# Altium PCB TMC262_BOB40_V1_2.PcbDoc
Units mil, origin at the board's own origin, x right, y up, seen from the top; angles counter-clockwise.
Board outline 1500 x 1200 mil, 4 copper layers (Top, GND, VM, Bottom), stack 27.719 mil thick; 33 components, 31 nets, 107 pads, 155 vias.
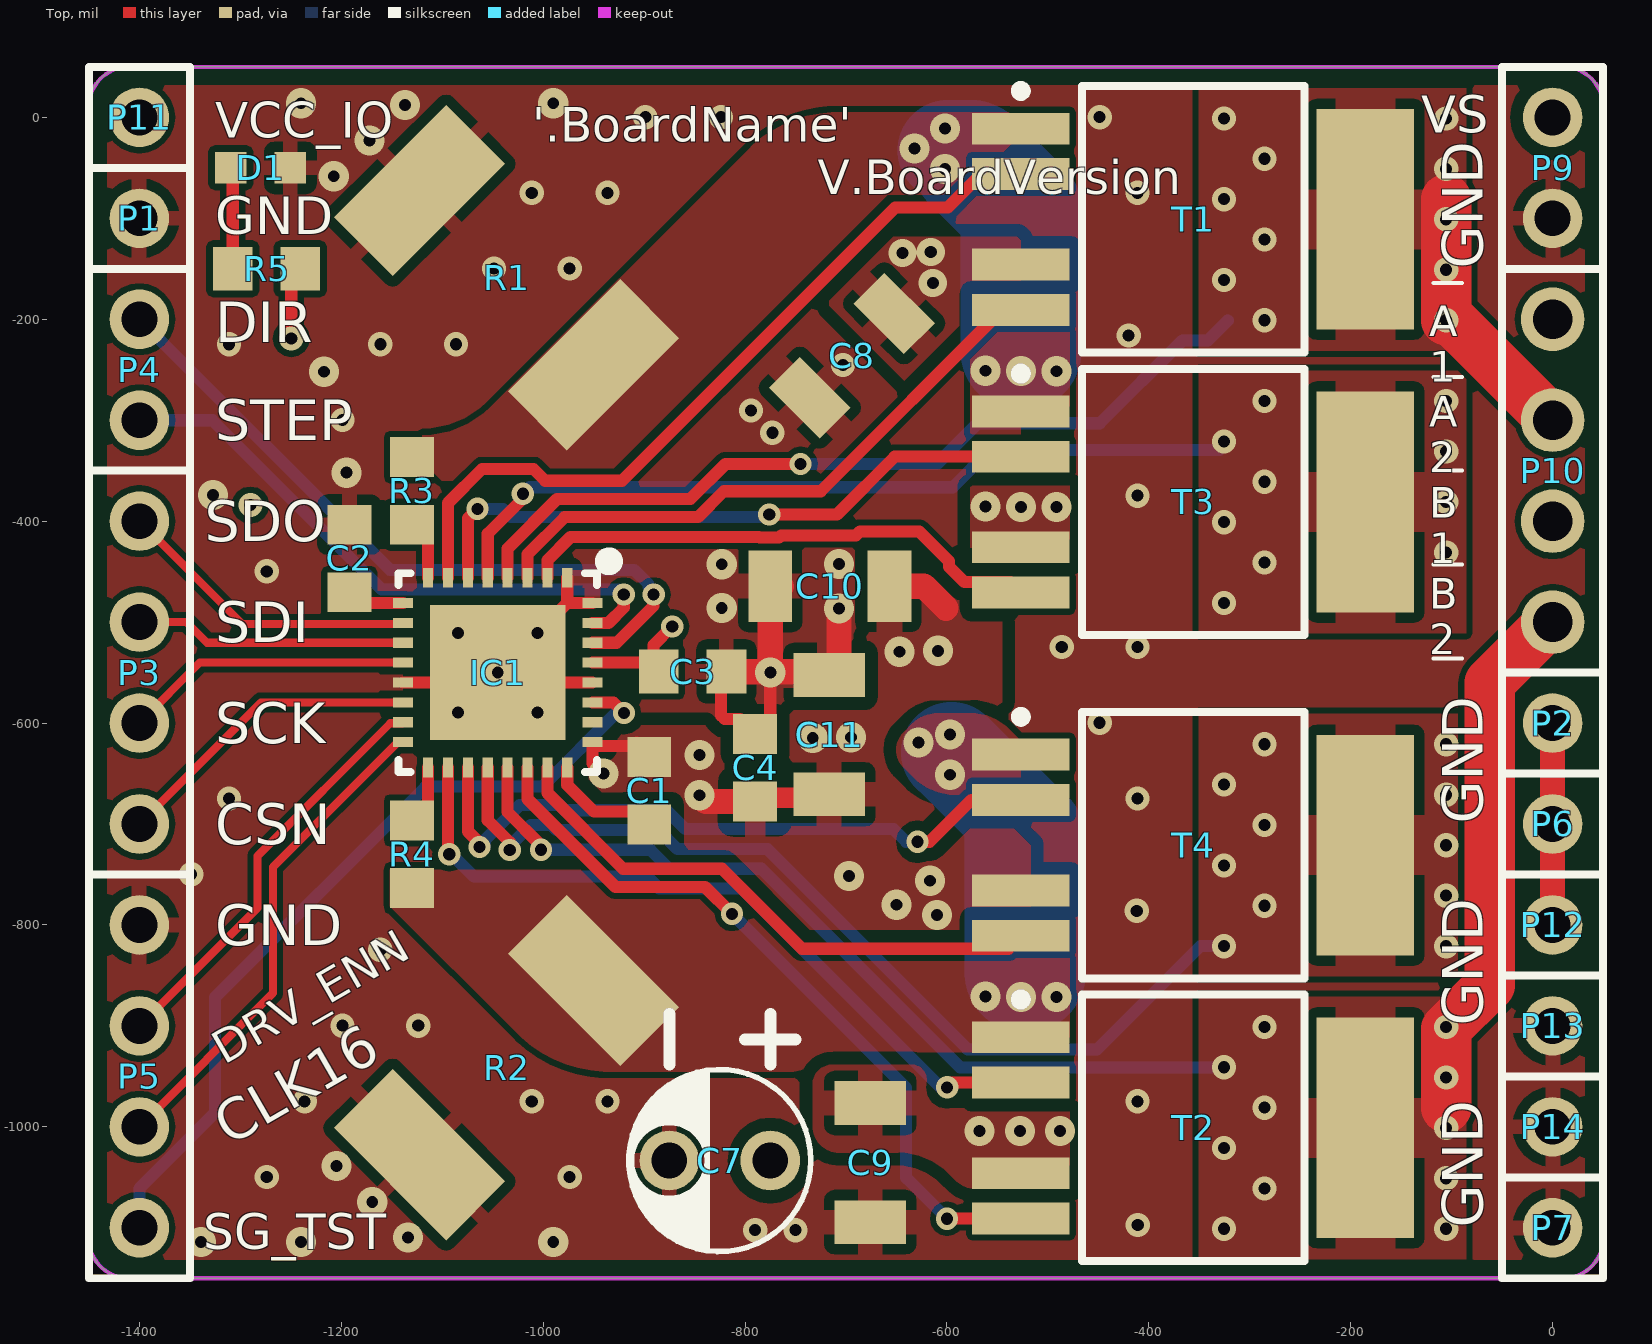
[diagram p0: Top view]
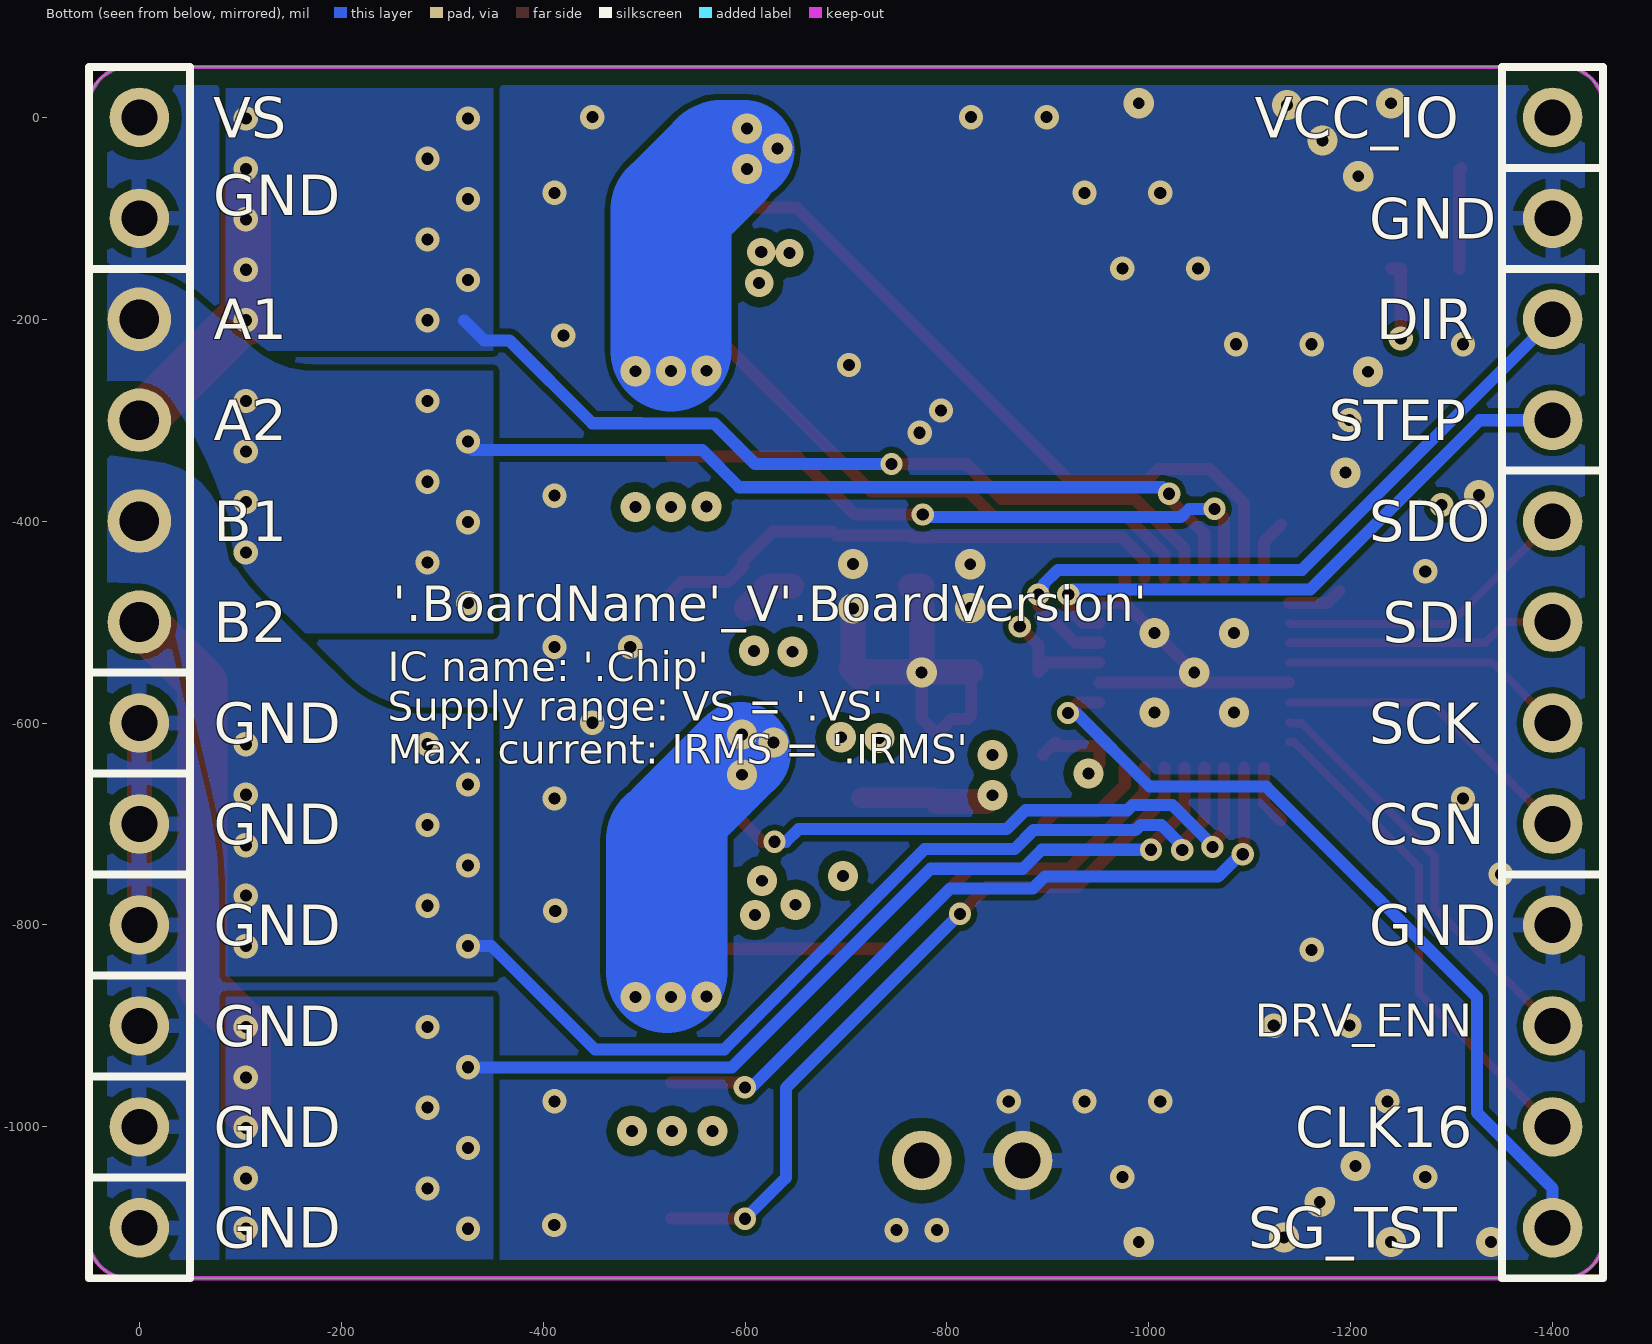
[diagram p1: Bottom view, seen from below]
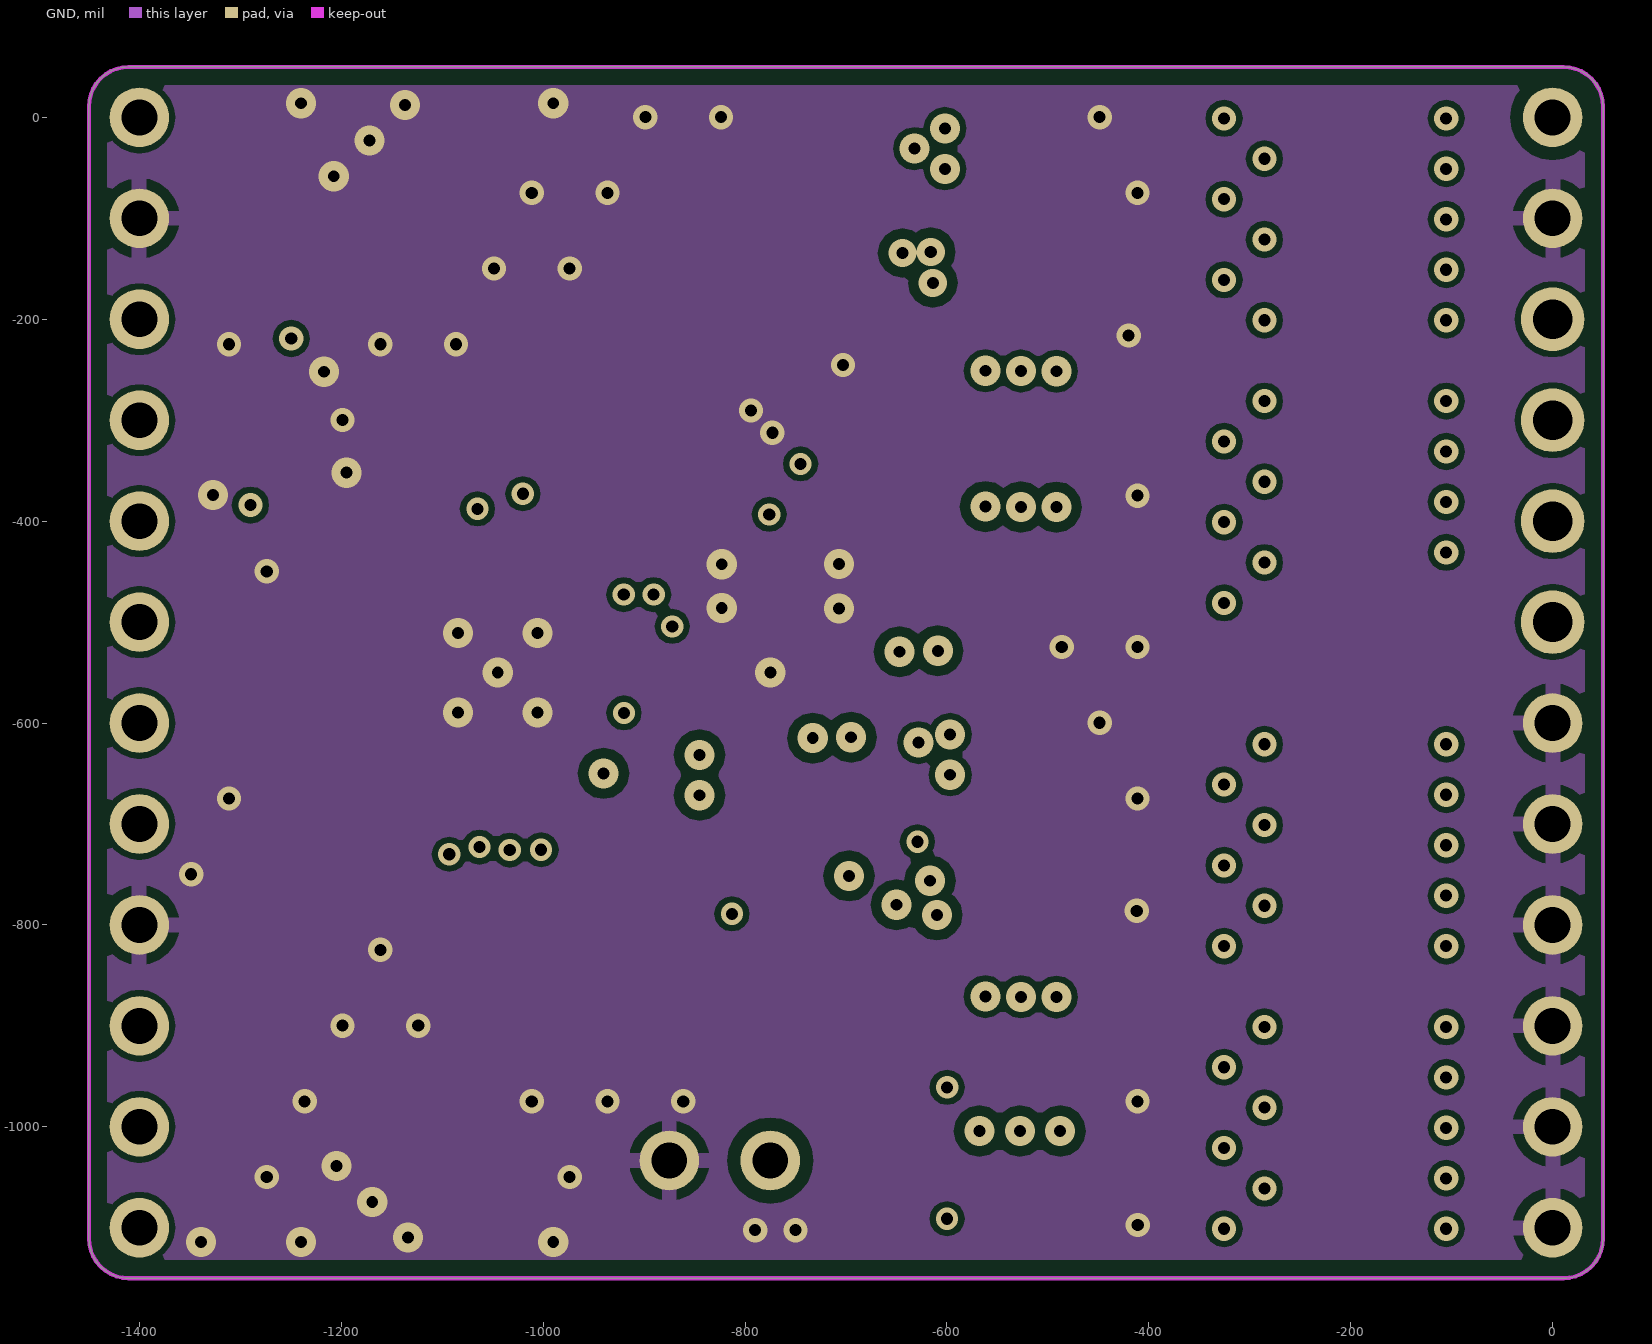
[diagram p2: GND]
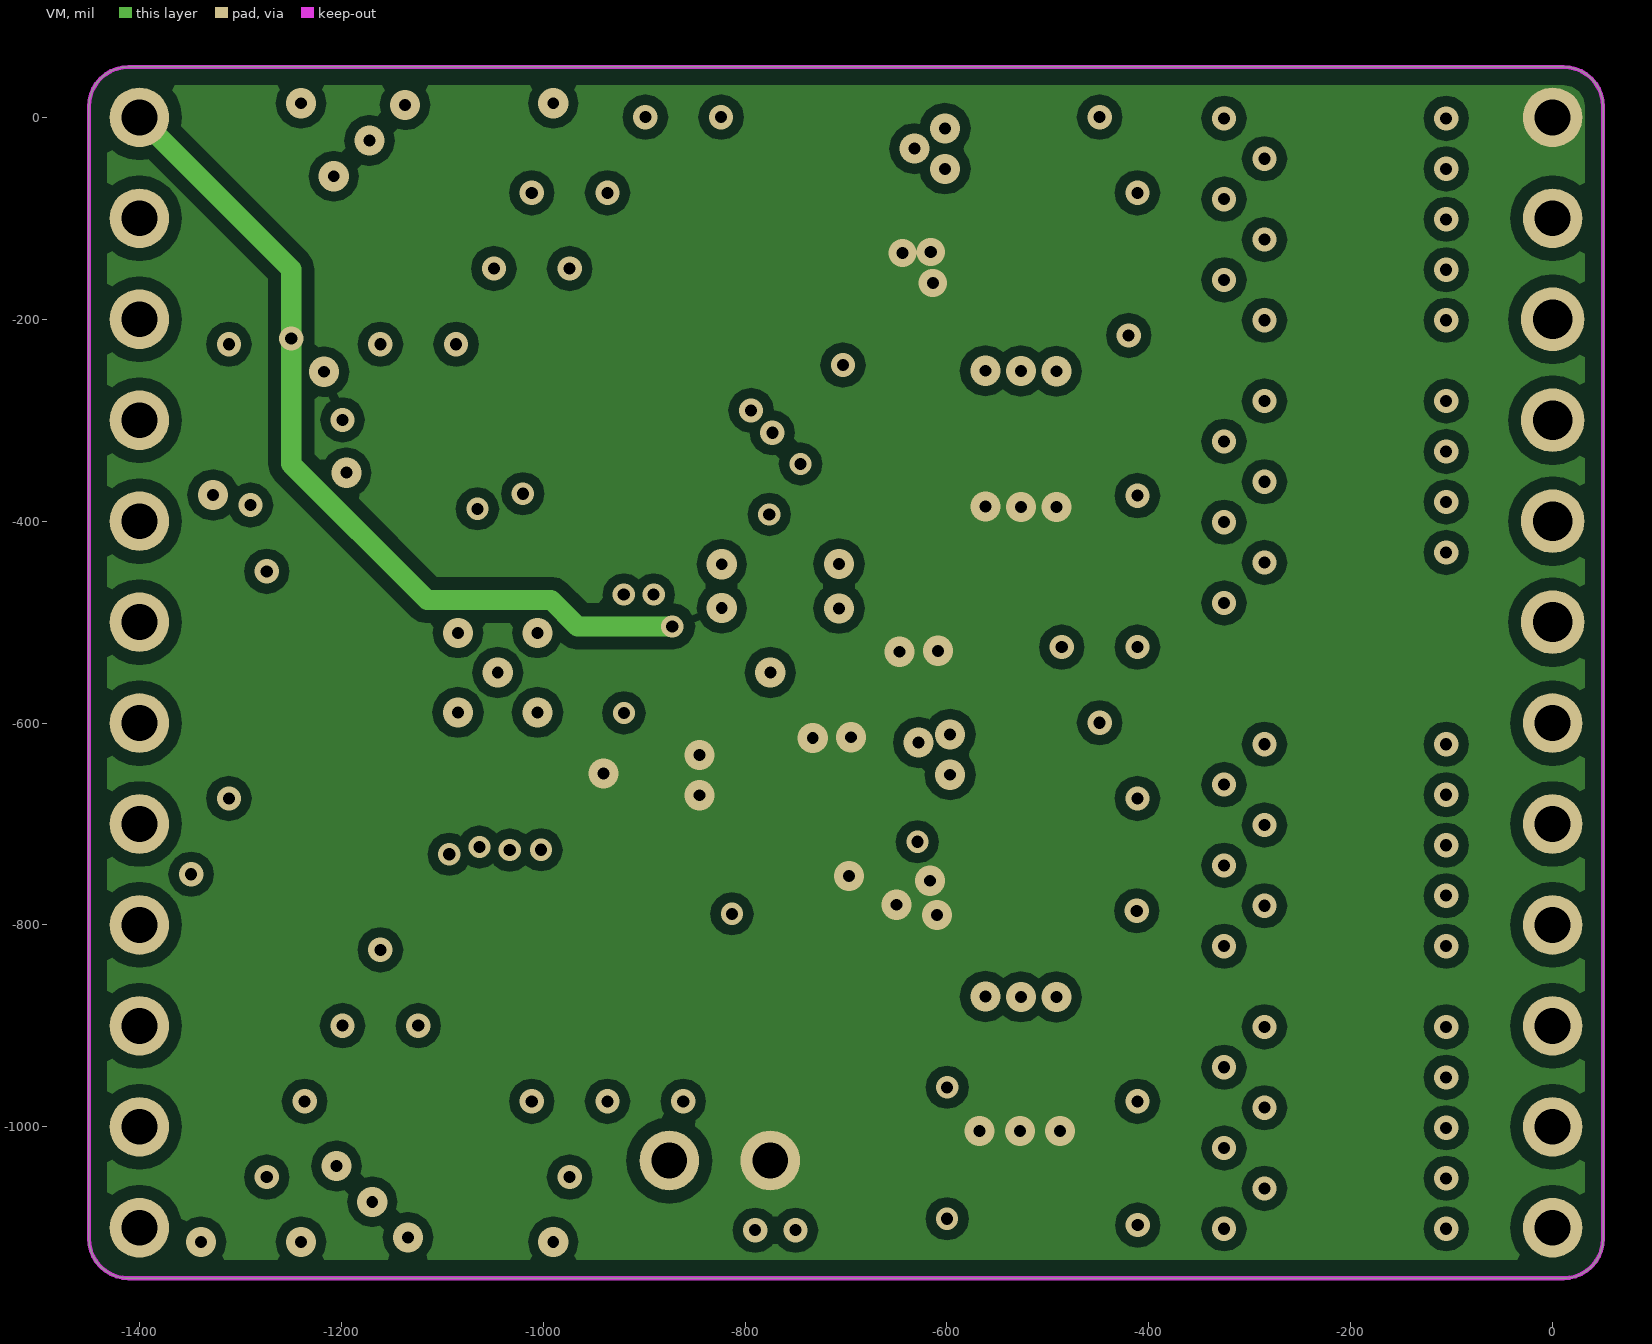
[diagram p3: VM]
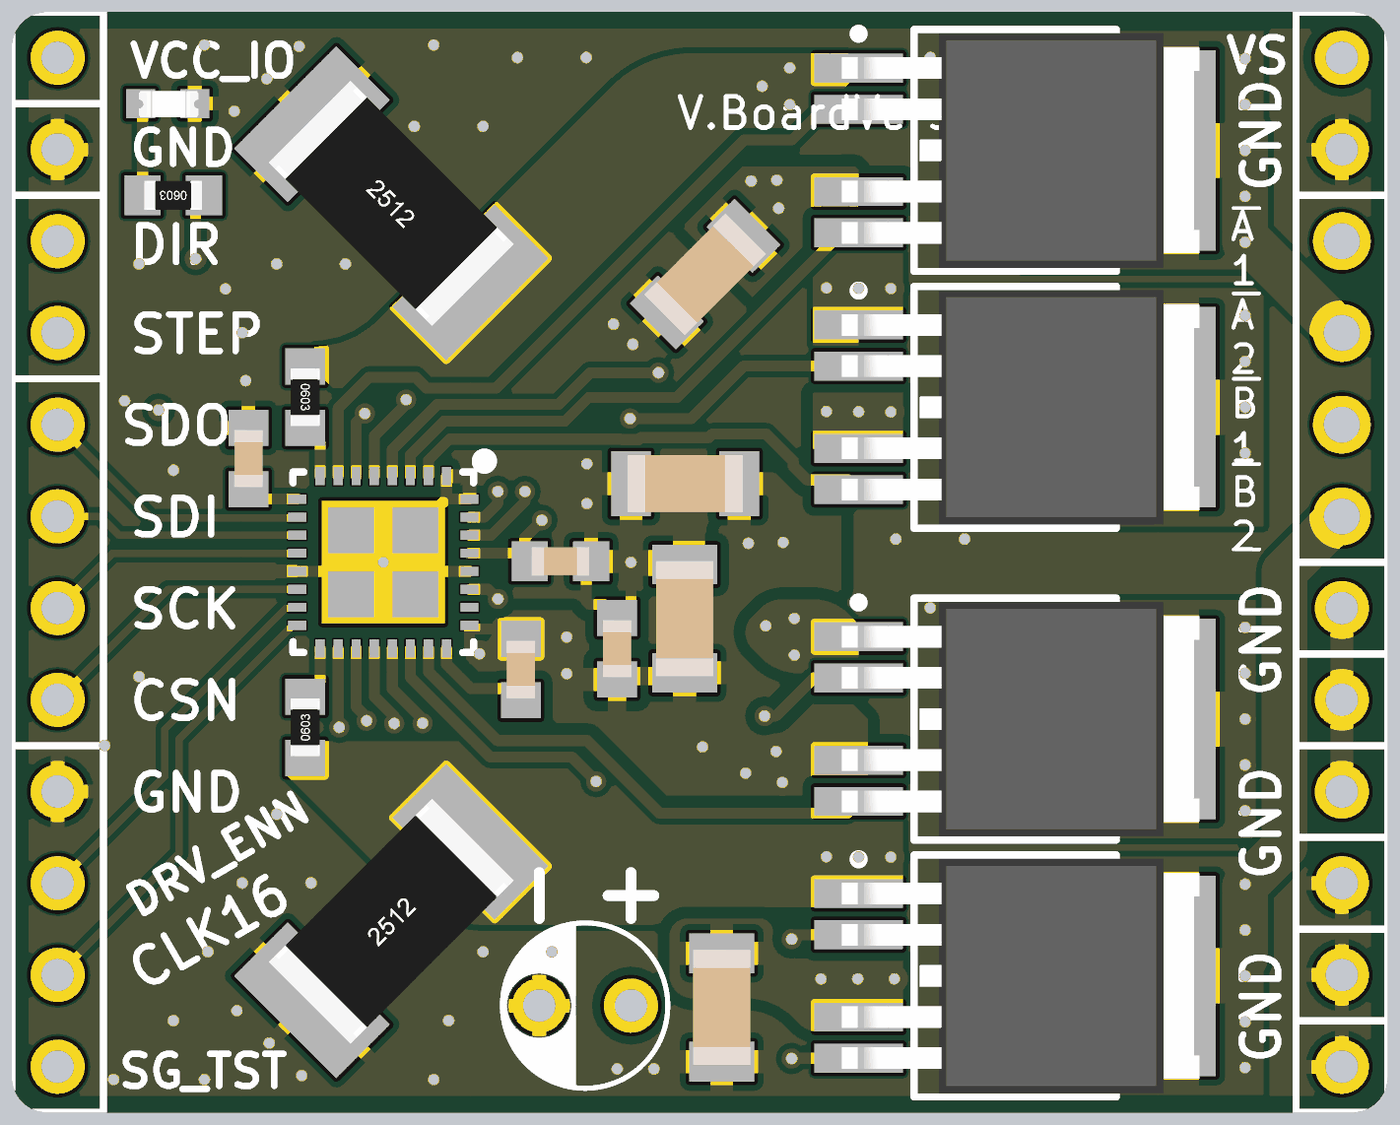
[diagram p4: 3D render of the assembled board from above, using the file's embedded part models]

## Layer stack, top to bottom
Top Solder: solder mask 0.4, Solder Resist, Dk 3.5
Top: signal copper 1.378
Dielectric 1: core 7.874, FR-4, Dk 4.8
GND: signal copper 0.689
Dielectric 2: prepreg 5, FR-4, Dk 4.2
VM: signal copper 1.4
Dielectric4: core 10, FR-4, Dk 4.2
Bottom: signal copper 1.378
Bottom Solder: solder mask 0.4, Solder Resist, Dk 3.5

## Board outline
-1450,-1110.63 -1450,10.63 cw(c-1410.63,10.63) -1410.63,50 10.63,50 cw(c10.63,10.63) 50,10.63 50,-1110.63 cw(c10.63,-1110.63) 10.63,-1150 -1410.63,-1150 cw(c-1410.63,-1110.63)

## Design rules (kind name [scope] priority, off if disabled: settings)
Clearance BoardOutlineClearance [OnLayer('Keep-Out Layer')] p1: gap=15.75 ignorepadtopadclearanceinfootprint=FALSE except(0: Arc-Hole Track-Hole SMDPad-Hole THPad-Hole Via-Hole Fill-Hole Poly-Hole Region-Hole Text-Hole)
Clearance VM_Clearance [InNet('VM') vs not (InComponent('Q1') or InComponent('Q2') or InComponent('Q3') or InComponent('Q4'))] p2: gap=12.7 ignorepadtopadclearanceinfootprint=TRUE except(0: Arc-Hole Track-Hole SMDPad-Hole THPad-Hole Via-Hole Fill-Hole Poly-Hole Region-Hole Text-Hole; 10: Via-Fill Via-Poly Via-Region)
Clearance "Fiducial Clearance" [HasFootprint('FIDUCIAL_40MIL')] p3: gap=26 ignorepadtopadclearanceinfootprint=FALSE except(0: Arc-Hole Track-Hole SMDPad-Hole THPad-Hole Via-Hole Fill-Hole Poly-Hole Region-Hole Text-Hole)
Clearance "Mounting Hole Clearance" [(HoleDiameter >= 110) And  IsPad  And ((PadYSize_AllLayers - HoleDiameter)  <=  1)] p4: gap=30 ignorepadtopadclearanceinfootprint=FALSE except(0: Arc-Hole Track-Hole SMDPad-Hole THPad-Hole Via-Hole Fill-Hole Poly-Hole Region-Hole Text-Hole)
Clearance [All] p5: gap=6 ignorepadtopadclearanceinfootprint=FALSE except(0: Arc-Hole Track-Hole SMDPad-Hole THPad-Hole Via-Hole Fill-Hole Poly-Hole Region-Hole Text-Hole)
ComponentClearance Pinheader2PinheaderClearance [InComponentClass('Pinheader') vs InComponentClass('Pinheader')] p1: gap=0 collisioncheckmode=3 verticalgap=0 showdistances=FALSE
ComponentClearance [All] p2: gap=10 collisioncheckmode=3 verticalgap=10 showdistances=FALSE
DiffPairsRouting [All] p1 off: maxlimit=10 minlimit=7.5 mostfreqgap=10 toplayer_prefgap=7.5 toplayer_minwidth=7.5 toplayer_maxwidth=7.5 toplayer_prefwidth=7.5 midlayer1_prefgap=7.5 midlayer1_minwidth=7.5 midlayer1_maxwidth=7.5 midlayer1_prefwidth=7.5 midlayer2_mingap=10 midlayer2_minwidth=15 midlayer2_maxwidth=15 midlayer2_prefwidth=15 bottomlayer_prefgap=7.5 bottomlayer_minwidth=7.5 bottomlayer_maxwidth=7.5 bottomlayer_prefwidth=7.5 maxuncoupledlength=500
HoleSize [All] p1: absolutevalues=TRUE maxlimit=100000 minlimit=11.81 maxpercent=80.000 minpercent=20.000
HoleToHoleClearance [All] p1: gap=8 allowstackedmicrovias=TRUE
MatchedLengths "SD_CARD MatchedLengths" [InNetClass('SD_CARD')] p1: tolerance=10 checknetsindiffpair=FALSE checkdiffpairvsdiffpair=TRUE checkxsignals=TRUE checkothers=TRUE
MinimumAnnularRing MinimumViaAnnualRing [All] p1: minimumring=4.92
MinimumSolderMaskSliver STM32_MinimumSolderMaskSliver [(InComponent('STM1') AND InComponent('STM2')) vs (InComponent('STM1') AND InComponent('STM2'))] p1: minsoldermaskwidth=1
MinimumSolderMaskSliver USB_HUB_MinimumSolderMaskSliver [InComponent('USB_HUB')] p2: minsoldermaskwidth=1
MinimumSolderMaskSliver [All] p3 off: minsoldermaskwidth=1.5
PasteMaskExpansion TestPadPasteMaskExpansion [HasFootprint('SMD_TP_2X2_ROUND')] p1: expansion=-78.74
PasteMaskExpansion [All] p2: expansion=0
PlaneConnect VM_PlaneConnect [OnLayer('VM') AND InNet('VM')] p1: planeconnectstyle=Relief reliefexpansion=20 reliefentries=4 reliefconductorwidth=20 reliefairgap=10
PlaneConnect [All] p2: planeconnectstyle=Relief reliefexpansion=20 reliefentries=4 reliefconductorwidth=10 reliefairgap=10
PolygonConnect currentSensePolygonConnect [InNetClass('CurrentSense')] p1: connectstyle=Direct reliefconductorwidth=10 reliefentries=4 polygonreliefangle="90 Angle" airgapwidth=10
PolygonConnect VSA_C1206_ConnectStyle [HasFootprint('C1206')] p2: connectstyle=Relief reliefconductorwidth=25 reliefentries=4 polygonreliefangle="90 Angle" airgapwidth=10
PolygonConnect VSA_C1_ConnectStyle [InNet('VM') AND (inComponent('C1') or HasFootprint('SOT114P991X239-6N'))] p3: connectstyle=Direct reliefconductorwidth=20 reliefentries=4 polygonreliefangle="90 Angle" airgapwidth=8
PolygonConnect VSAViaConnectStyle [InNet('VM') AND IsVia] p4: connectstyle=Direct reliefconductorwidth=20 reliefentries=4 polygonreliefangle="90 Angle" airgapwidth=8
PolygonConnect VSAConnectStyle [InNet('VM')] p5: thpad.connectstyle=Direct thpad.reliefconductorwidth=20 thpad.reliefentries=4 thpad.polygonreliefangle="90 Angle" thpad.airgapwidth=15 smdpad.connectstyle=Relief smdpad.reliefconductorwidth=20 smdpad.reliefentries=4 smdpad.polygonreliefangle="90 Angle" smdpad.airgapwidth=15 via.connectstyle=Direct via.reliefconductorwidth=20 via.reliefentries=4 via.polygonreliefangle="90 Angle" via.airgapwidth=15
PolygonConnect MotorPhaseConnectStyle [InNetClass('MotorPower')] p6: thpad.connectstyle=Direct thpad.reliefconductorwidth=10 thpad.reliefentries=4 thpad.polygonreliefangle="90 Angle" thpad.airgapwidth=10 smdpad.connectstyle=Relief smdpad.reliefconductorwidth=60 smdpad.reliefentries=4 smdpad.polygonreliefangle="90 Angle" smdpad.airgapwidth=10 via.connectstyle=Direct via.reliefconductorwidth=10 via.reliefentries=4 via.polygonreliefangle="90 Angle" via.airgapwidth=10
PolygonConnect ThermalVias [IsVia] p7: connectstyle=Direct reliefconductorwidth=10 reliefentries=4 polygonreliefangle="90 Angle" airgapwidth=10
PolygonConnect [All] p8: connectstyle=Relief reliefconductorwidth=15 reliefentries=4 polygonreliefangle="90 Angle" airgapwidth=10
RoutingVias [All] p1: holewidth=12 width=22 viastyle="Through Hole" minholewidth=12 minwidth=22 maxholewidth=12 maxwidth=50
ShortCircuit [All] p1 off: allowed=FALSE
SilkToBoardRegionClearance [All] p1 off:
SilkToSilkClearance [All] p1 off: silktosilkclearance=10
SilkToSolderMaskClearance [IsPad] p1 off: minsilkscreentomaskgap=10 clearancetoexposedcopper=TRUE
SolderMaskExpansion FiducialSolderMaskExpansion [HasFootprint('FIDUCIAL_40MIL')] p1: expansion=26
SolderMaskExpansion [All] p2: expansion=4
UnRoutedNet [All] p1 off:
Width VIN_Width [InNetClass('PWR_VIN')] p1: maxlimit=300 minlimit=200 preferedwidth=210
Width Other_Width [All] p2: maxlimit=100000 minlimit=8 preferedwidth=11.81 minimp=50.000000 maximp=50.000000 favimp=50.000000
18 further rules are at their usual default settings.

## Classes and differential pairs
net class MotorPower: A1 A2 B1 B2
net class CurrentSense: SRA SRB
differential pair class USB_DIFF: STM_USB STM_USB_D

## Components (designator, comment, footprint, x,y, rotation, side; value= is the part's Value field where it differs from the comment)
C1 "220nF/16V/10%" C0603 -895,-667 r270 top
C2 "470nF/16V/10%" C0603 -1191.94,-436.93 r90 top
C3 "100nF/16V/10%" C0603 -851.94,-549 r0 top
C4 "100nF/50V/20%" C0603 -790.12,-644.21 r270 top
C7 "Cap Pol1" EXT_POL_CAP -775,-1033.36 r90 top value=TBD
C8 "10uF/50V/10%" C1206 -694.08,-235.96 r45 top
C9 "10uF/50V/10%" C1206 -676,-1035.36 r90 top
C10 "10uF/50V/10%" C1206 -715.94,-464.37 r0 top
C11 "10uF/50V/10%" C1206 -716.51,-611.52 r270 top
D1 "LED, Blue, SMD, 20mA, 2.8V, 465 nm" LED_0603 -1280,-50 r0 top
IC1 "TMC262-LA" TMC262_QFN32_0.5_5.0X5.0 -1045,-550 r180 top
P1 "GND" TH_PIN -1400,-100 r90 top
P2 "GND" TH_PIN 0,-600 r0 top
P3 "SPI" 4_PIN_THT -1400,-700 r0 top
P4 "STEP/DIR" 2_PIN_THT -1400,-300 r0 top
P5 "MISC" 4_PIN_THT -1400,-1100 r0 top
P6 "GND" TH_PIN 0,-700 r0 top
P7 "GND" TH_PIN 0,-1100 r0 top
P9 "VM" 2_PIN_THT 0,-100 r0 top
P10 "MAB" 4_PIN_THT_1mm_hole 0,-200 r180 top
P11 "GND" TH_PIN -1400,0 r90 top
P12 "GND" TH_PIN 0,-800 r0 top
P13 "GND" TH_PIN 0,-900 r0 top
P14 "GND" TH_PIN 0,-1000 r0 top
R1 ".075R / 2W / 1%" R2512 -1036.3,-158.75 r315 top
R2 ".075R / 2W / 1%" R2512 -1036.3,-941.25 r45 top
R3 "10R / 1%" R0603 -1130,-370 r270 top
R4 "10R / 1%" R0603 -1130,-730 r90 top
R5 "1k" R0603 -1274,-150 r180 top
T1 "FDD8424H" SOT114P991X239-6N -356.14,-101 r0 top
T2 "FDD8424H" SOT114P991X239-6N -356.14,-1001 r0 top
T3 "FDD8424H" SOT114P991X239-6N -356.14,-381 r0 top
T4 "FDD8424H" SOT114P991X239-6N -356.14,-721 r0 top

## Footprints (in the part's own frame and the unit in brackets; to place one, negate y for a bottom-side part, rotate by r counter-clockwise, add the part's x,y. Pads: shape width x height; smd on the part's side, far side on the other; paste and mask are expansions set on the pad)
2_PIN_THT [mm]
  round 1.5 hole 0.9: 1(0,0) 2(0,2.54)
  silkscreen extent -1.27,-1.27 1.27,3.81
4_PIN_THT [mm]
  round 1.5 hole 0.9: 1(0,0) 2(0,2.54) 3(0,5.08) 4(0,7.62)
  silkscreen extent -1.27,-1.27 1.27,8.89
4_PIN_THT_1mm_hole [mm]
  round 1.6 hole 1: 1(0,0) 2(0,2.54) 3(0,5.08) 4(0,7.62)
  silkscreen extent -1.27,-1.27 1.27,8.89
C0603 [mm] "0603 ceramic capacitor"
  rect 1x1.1 smd: 1(-0.85,0) 2(0.85,0)
  body extent -0.8,-0.4 0.8,0.4, height 0.8
C1206 [mm] "1206 ceramic capacitor"
  rect 1.1x1.8 smd: 1(-1.5,0) 2(1.5,0)
  body extent -1.6,-0.8 1.6,0.8, height 0.76
EXT_POL_CAP [mm]
  round 1.5 hole 0.9: 1(0,0) 2(0,2.54)
  silkscreen extent -2.29,-1.02 3.68,3.56
LED_0603 [mm]
  rect 0.8x0.8 smd: 1(-0.75,0) 2(0.75,0)
  body extent -0.8,-0.38 0.85,0.35, height 0.68
R0603 [mm] "0603 resistor"
  rect 1x1.1 smd: 1(-0.85,0) 2(0.85,0)
  body extent -0.8,-0.4 0.8,0.4, height 0.45
R2512 [mm] "2512 resistor"
  rect 2.1x4 smd: 1(-3.1,0) 2(3.1,0)
  body extent -3.2,-1.6 3.2,1.6, height 0.59
SOT114P991X239-6N [mm] "SOT223, 6-Leads, Body 6,54x9,91mm (avg), Pitch 1,14mm, IPC Medium Density"
  rect 2.45x0.8 smd: 1(-4.335,2.28) 2(-4.335,1.14) 3(-4.335,-1.14) 4(-4.335,-2.28)
  rect 2.45x5.55 smd: 5(4.335,0)
  silkscreen extent -4.46,-3.35 2.8,3.35, body extent -4.8,-3.25 5.1,3.25, height 2.3
TH_PIN [mm]
  round 1.5 hole 0.9: 1(0,0)
  silkscreen extent -1.27,-1.27 1.27,1.27
TMC262_QFN32_0.5_5.0X5.0 [mm]
  rect 0.254x0.5 smd mask+0.046: 1(-1.75,-2.385) 2(-1.25,-2.385) 3(-0.75,-2.385) 4(-0.25,-2.385) 5(0.25,-2.385) 6(0.75,-2.385) 7(1.25,-2.385) 8(1.75,-2.385) 17(1.75,2.385) 18(1.25,2.385) 19(0.75,2.385) 20(0.25,2.385) 21(-0.25,2.385) 22(-0.75,2.385) 23(-1.25,2.385) 24(-1.75,2.385)
  rect 0.5x0.254 smd mask+0.046: 9(2.385,-1.75) 10(2.385,-1.25) 11(2.385,-0.75) 12(2.385,-0.25) 13(2.385,0.25) 14(2.385,0.75) 15(2.385,1.25) 16(2.385,1.75) 25(-2.385,1.75) 26(-2.385,1.25) 27(-2.385,0.75) 28(-2.385,0.25) 29(-2.385,-0.25) 30(-2.385,-0.75) 31(-2.385,-1.25) 32(-2.385,-1.75)
  rect 3.4x3.4 smd paste-254: 33(0,0)
  silkscreen extent -2.9,-2.9 2.5,2.5, body extent -2.5,-2.5 2.5,2.5, height 0.9

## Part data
C1: library part Capacitor, "Ceramic capacitor", Capacitance=220nF, MPN=MC0603B224K160CT, VoltageRating=16V
C2: library part Capacitor, "Ceramic capacitor", Capacitance=470nF, MPN=MC0603X474K160CT, VoltageRating=16V
C3: library part Capacitor, "Ceramic capacitor", Capacitance=100nF, MPN=MC0603B104K160CT, VoltageRating=16V
C4: library part Capacitor, "Ceramic capacitor", Capacitance=100nF, MPN=MC0603F104M500CT, VoltageRating=50V
C7: "Polarized Capacitor (Radial)"
C8 C9 C10 C11: library part "10 µF, 50 V, ± 10%, X5R, 1206 [3216 Metric]", "SMD Multilayer Ceramic Capacitor, 1206 [3216 Metric],10 µF, 50 V, ± 10%, X5R, GRM Series", Capacitance=10uF, MPN=GRM31CR61H106KA12L, VoltageRating=50V
D1: Colour=Blue, Current rating=20mA, MPN=LTST-C191TBKT-5A
IC1: "Energy saving high resolution microstepping two phase stepper driver with Step/Dir, SPI, up to 60V, QFN32(5x5)", Manufacturer=TRINAMIC
P1 P2 P6 P7 P11 P12 P13 P14: library part PIN
P3 P5: library part "Header 4", "Header, 4-Pin"
P4 P9: library part "Header 2", "Header, 2-Pin"
P10: library part "Wire-To-Board Connector, 2.5 mm, 4 Contacts, Header, EH Series, Through Hole, 1 Rows", "Wire-To-Board Connector, 2.5 mm, 4 Contacts, Header, EH Series, Through Hole, 1 Rows", MPN=B4B-EH-A
R1 R2: library part ".075 OHM 2W 1% Current Sense Resistor", "SMD Current Sense Resistor, 0.075 ohm, 2 W, 2512 [6432 Metric], ± 1%, TLR Series", MPN=TLR3A20WR075FTDG, PowerRating=2W, Resistance=.075R
R3 R4: library part ".05 OHM 2W 1% Current Sense Resistor", "SMD Chip Resistor, Thick Film, 10 ohm, 50 V, 0603 [1608 Metric], 100 mW, ± 1%, MCWR Series", MPN=MCWR06X10R0FTL, PowerRating=100mW, Resistance=10R
R5: library part "1 kohm, 50 V, 0603 [1608 Metric], 63 mW, ± 1%, MC Series", "1 kohm, 50 V, 0603 [1608 Metric], 63 mW, ± 1%, MC Series", MPN=MC0063W060311K, PowerRating=63mW, Temp coefficient=*ppm, VoltageRating=50V
T1 T2 T3 T4: "Dual MOSFET, N and P Channel, 9 A, 40 V, 0.019 ohm, 10 V, 1.7 V"

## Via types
v1: diameter 24, hole 12, Top to Bottom, tented both sides, 53 vias
v2: diameter 29.81, hole 11.81, Top to Bottom, tented both sides, 53 vias
v3: diameter 24.1, hole 12, Top to Bottom, tented both sides, 30 vias
v4: diameter 22, hole 12, Top to Bottom, tented both sides, 16 vias
v5: diameter 28, hole 12, Top to Bottom, tented both sides, 3 vias

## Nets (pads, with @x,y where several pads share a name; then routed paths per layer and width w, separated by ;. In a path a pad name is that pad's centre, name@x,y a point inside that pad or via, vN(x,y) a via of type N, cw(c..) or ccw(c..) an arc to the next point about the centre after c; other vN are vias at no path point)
A1: IC1.5 P10.1 T3.5 | length 817.5
  Top w12: IC1.5 -1054.84,-412.52 -1020.12,-377.8 v4(-1020.12,-372.8)
  Bottom w12: v4(-1020.12,-372.8) -1013.68,-366.36 -594.3,-366.36 -557.3,-329.36 -330.17,-329.36 v1@-321.81,-321
  other v1: -325.47,-481 -285.47,-441 -105.47,-431 -325.47,-401 -105.47,-381 -285.47,-361 -105.47,-331 -325.47,-321 -285.47,-281 -105.47,-281
A2: IC1.4 P10.2 T1.5 | length 1110.8
  Top w12: IC1.4 -1035.16,-427 -986.21,-378.06 -854.15,-378.06 -819.46,-343.36 v4(-745,-343.36)
  Top w50: -105.47,-81 -105.47,-121 -105.47,-161 v1(-105.47,-201) -105.47,-195.32 P10.2@0,-300.79
  Bottom w12: v4(-745,-343.36) -609.95,-343.36 -569.83,-303.24 -496.99,-303.24 -496.75,-303 -448.64,-303 -366.64,-221 -341.57,-221 -321.81,-201.24
  other v1: -285.47,-201 -325.47,-161 -105.47,-151 -285.47,-121 -105.47,-101 -325.47,-81 -105.47,-51 -285.47,-41 -325.47,-1 -105.47,-1
B1: IC1.20 P10.3 T4.5 | length 945.6
  Top w12: IC1.20 -1054.84,-696.28 -1033.12,-718.01 v4(-1033.12,-725.8)
  Bottom w12: v4(-1033.12,-725.8) -1033.12,-721.73 -1012.32,-700.94 -991.94,-700.94 -986.94,-705.94 -885.84,-705.94 -867.04,-724.74 -777.94,-724.74 -579.45,-923.24 -451.24,-923.24 -349,-821 v1(-325.47,-821)
  other v1: -105.47,-821 -285.47,-781 -105.47,-771 -325.47,-741 -105.47,-721 -285.47,-701 -105.47,-671 -325.47,-661 -285.47,-621 -105.47,-621
B2: IC1.21 P10.4 T2.5 | length 1388.5
  Top w12: IC1.21 -1035.16,-688.25 -1002.13,-721.28 v4(-1002.13,-725.54)
  Top w50: -105.47,-981 -105.47,-902.83 -62.47,-859.83 -62.47,-560.11 P10.4@0,-497.64
  Bottom w12: v4(-1002.13,-725.54) -893.96,-725.54 -875.16,-744.34 -783.8,-744.34 -586.9,-941.24 -325.71,-941.24 v1(-325.47,-941)
  other v1: -325.47,-1101 -105.47,-1101 -285.47,-1061 -105.47,-1051 -325.47,-1021 -105.47,-1001 -285.47,-981 -105.47,-951 -285.47,-901 -105.47,-901
CLK16: IC1.16 P5.2 | length 492.1
  Top w8: P5.2 -1267.49,-867.49 -1267.49,-742.64 -1143.74,-618.9 IC1.16
CSN: IC1.14 P3.1 | length 311
  Top w8: P3.1 -1279.53,-579.53 IC1.14
DIR: IC1.30 P4.2 | length 712.3
  Top w12: IC1.30 -927.23,-520.47 -890.52,-483.76 v4(-890.52,-472.8)
  Bottom w12: P4.2 -1151.8,-448.2 -909.93,-448.2 -895.52,-462.61 -895.52,-465.09 -890.52,-470.09 v4(-890.52,-472.8)
DRV_ENN: IC1.15 P5.3 | length 415.7
  Top w8: P5.3 -1283.09,-783.09 -1283.09,-731.84 -1151.46,-600.22 -1139.9,-600.22 IC1.15
GND: C2.2 C3.2 C4.1 C7.2 C8.1 C9.1 C10.1 C11.1 D1.2 IC1.1 IC1.13 IC1.28 IC1.32 IC1.33 P1.1 P2.1 P5.4 P6.1 P7.1 P9.1 P12.1 P13.1 P14.1 R1.1 R2.1 | length 966.9
  Top w12: IC1.13 -1054.84,-559.84 v2(-1045,-550) ; IC1.1 -976.1,-481.1 ; IC1.28 -1035.16,-559.84 v2(-1045,-550) ; IC1.32 -976.1,-481.1 ; C3.2@-823.64,-549.21 -823.64,-592.4 -820.17,-595.87 -805,-595.87 C4.1 -774.99,-595.62 v2(-774.99,-550) ; v2(-1045,-550) -976.1,-481.1
  Top w25: C3.2 -823.64,-549 -823.64,-549.21 v2@-774.99,-549.21 ; C10.1 C10.1@-764.06,-464.37 ; v2(-774.99,-550) v2@-774.99,-549.21 ; C10.1@-774.99,-484.06 v2@-774.99,-549.21 ; v2(-707,-486.36) -707,-543.95 -705,-545.95 -715,-555.94 -715,-549.21 v2@-774.99,-549.21 ; P12.1 P6.1 P2.1
  other v1: -790,-1102.36 -750,-1102.36 -411,-1097.36 -412,-786 -773,-312.36 -794,-290.36 -703,-245.36 -420,-216
  other v2: -1339,-1113.99 -1240,-1113.99 -990,-1113.99 -1133.95,-1109.62 -1169.31,-1074.27 -1204.66,-1038.91 -1084.37,-589.37 -1005.63,-589.37 -1084.37,-510.63 -1005.63,-510.63 -823.11,-486.07 -823.11,-442.68 -707,-442.36 -1327.04,-374 -1195,-352 -1217,-252 -1207.45,-58.3 -1172.1,-22.95 -1136.74,12.41 -1240,14 -990,14
  other v3: -1273.77,-1049.73 -973.77,-1049.73 -1236.27,-974.73 -1011.27,-974.73 -936.27,-974.73 -861.27,-974.73 -411.27,-974.73 -1198.77,-899.73 -1123.77,-899.73 -1161.27,-824.73 -1348.77,-749.73 -1311.27,-674.73 -411.27,-674.73 -448.77,-599.73 -486.27,-524.73 -411.27,-524.73 -1273.77,-449.73 -411.27,-374.73 -1198.77,-299.73 -1311.27,-224.73 -1161.27,-224.73 -1086.27,-224.73 -1048.77,-149.73 -973.77,-149.73 -1011.27,-74.73 -936.27,-74.73 -411.27,-74.73 -898.77,0.27 -823.77,0.27 -448.77,0.27
HA1: IC1.2 T3.4 | length 526.9
  Top w12: IC1.2 -995.79,-438.69 -972.87,-415.77 -786.11,-415.77 -785.53,-416.36 -766.47,-416.36 -764.17,-414.06 -690.11,-414.06 -686.29,-410.24 -627.49,-410.24 -598,-439.73 -598,-445.11 -582.78,-460.33 -537.24,-460.33 T3.4
HA2: IC1.3 T1.4 | length 612.2
  Top w12: IC1.3 -1015.47,-432.77 -978.75,-396.06 -846.69,-396.06 -821,-370.36 -725,-370.36 -545.4,-190.76 T1.4
HB1: IC1.23 T4.4 | length 563.5
  Top w12: IC1.23 -995.79,-669.37 -920.82,-744.34 -822.87,-744.34 -743.6,-823.61 -539.18,-823.61 T4.4@-526.81,-811.24
HB2: IC1.22 T2.4 | length 744.4
  Top w12: IC1.22 -1015.47,-675.14 -928.27,-762.34 -839.66,-762.34 v4(-813,-789) ; v4(-599.81,-1091.05) -599.52,-1090.76 T2.4
  Bottom w12: v4(-813,-789) -640.41,-961.59 -640.41,-1050.45 v4(-599.81,-1091.05)
LA1: IC1.6 T3.2 | length 638.5
  Top w12: IC1.6 -1074.44,-456.02 -1074.44,-397.12 v4(-1065.12,-387.8) ; v4(-776,-393.36) -709,-393.36 -651.76,-336.12 T3.2
  Bottom w12: v4(-1065.12,-387.8) -1039.91,-387.8 -1031.91,-395.8 -778.43,-395.8 v4(-776,-393.36)
LA2: IC1.7 T1.2 | length 786.2
  Top w12: IC1.7 -1094.21,-382.1 -1060.31,-348.2 -1009.73,-348.2 -997.92,-360 -921.89,-360 -651.25,-89.36 -599.16,-89.36 -565.91,-56.12 T1.2
LB1: IC1.19 T4.2 | length 673.5
  Top w12: IC1.19 -1074.53,-707.39 -1063.12,-718.8 v4(-1063.12,-722.8) ; v4(-629.31,-717.63) -617.27,-717.63 -575.76,-676.12 T4.2
  Bottom w12: v4(-1063.12,-722.8) -1057.72,-722.8 -1057.72,-715.61 -1023.45,-681.34 -983.82,-681.34 -978.82,-686.34 -877.73,-686.34 -858.92,-705.14 -652.9,-705.14 -640.41,-717.63 v4(-629.31,-717.63)
LB2: IC1.18 T2.2 | length 750.4
  Top w12: IC1.18 -1094.21,-728.83 v4(-1093.05,-730) ; v4(-599.8,-960.87) -595.04,-956.12 T2.2
  Bottom w12: v4(-1093.05,-730) -1090.7,-730 -1068.7,-752 -897,-752 -885.06,-763.94 -803.27,-763.94 -606.34,-960.87 v4(-599.8,-960.87)
NetC1_2: C1.2 IC1.24 | length 114.7
  Top w12: IC1.24 -976.1,-661.34 -949.64,-687.8 -907.67,-687.8 C1.2
NetC2_1: C2.1 IC1.9 | length 54.7
  Top w12: C2.1@-1188.64,-469.21 -1176.75,-481.1 IC1.9
NetD1_1: D1.1 R5.2 | length 100.9
  Top w12: D1.1 -1307.46,-52.06 R5.2
NetIC1_8: IC1.8 R3.2 | length 59.7
  Top w12: R3.2@-1131,-403.46 -1113.9,-420.57 IC1.8
NetIC1_17: IC1.17 R4.2 | length 59.7
  Top w12: R4.2@-1131,-696.54 -1113.9,-679.43 IC1.17
SCK: IC1.12 P3.2 | length 285.9
  Top w8: P3.2 -1340.16,-540.16 IC1.12
SDI: IC1.11 P3.3 | length 269.6
  Top w8: P3.3 -1353.55,-500 -1333.07,-520.48 IC1.11
SDO: IC1.10 P3.4 | length 303.6
  Top w8: P3.4 -1298.32,-501.68 -1139.79,-501.68 IC1.10
SG_TST: IC1.27 P5.1 | length 816.6
  Top w12: IC1.27 -930.47,-579.53 v4(-919.99,-590)
  Bottom w12: P5.1 -1400,-1060.99 -1325,-985.99 -1325,-871.6 -1116.4,-663 -1000.85,-663 -927.85,-590 v4(-919.99,-590)
SRA: R1.2 R3.1 T1.1 T3.1 | length 231.7
  Bottom w100: -599.08,-32.86 -574.5,-32.86
  Bottom w120: -574.5,-43.86 -526.81,-91.55 -526.81,-231.24
  other v2: -526.81,-251.24 -491.67,-251.47 -561.94,-251 -601.94,-51 -631.94,-31 -601.94,-11
SRB: R2.2 R4.1 T2.1 T4.1 | length 228.8
  Bottom w100: -595.35,-628.97 -526.32,-698
  Bottom w120: -522.39,-846.82 -522.39,-715.65
  other v2: -526.81,-871.24 -491.67,-871.47 -561.94,-871 -596.81,-651.24 -628,-619.36 -596.81,-611.24
STEP: IC1.31 P4.1 | length 601.6
  Top w12: IC1.31 -935.26,-500.79 -920.12,-485.65 v4(-920.12,-472.8)
  Bottom w12: P4.1 -1327.72,-300 -1159.92,-467.8 -925.12,-467.8 v4(-920.12,-472.8)
VCC_IO: C3.1 IC1.29 P11.1 R5.1 | length 1044.7
  Top w12: v1(-1249.51,-219.06) -1249.51,-150 R5.1 ; IC1.29 -899.62,-540.16 -890.57,-549.21 -890.57,-522.68 v4(-872.1,-504.21)
  VM w20: P11.1 -1249.51,-150.49 v1(-1249.51,-219.06) -1249.51,-343.46 -1114.84,-478.13 -992.17,-478.13 -966.09,-504.21 v4(-872.1,-504.21)
VM: C1.1 C4.2 C7.1 C8.2 C9.2 C10.2 C11.2 IC1.25 P9.2 T1.3 T2.3 T3.3 T4.3 | length 280.7
  Top w12: v2@-942.1,-649.21 -951.1,-640.21 -951.1,-622.92 -910.91,-622.92 -907.26,-619.27 C1.1@-895,-631.54
  Top w20: C4.2 -786.5,-674.06 C11.2@-715,-674.06
  Top w25: v2(-845,-671.54) -838.86,-677.68 C4.2 ; C10.2@-645.95,-464.37 -622.86,-464.37 -601.06,-486.18
  other v2: -567.81,-1004.24 -527.81,-1004.24 -487.81,-1004.24 -610,-790 -650,-780 -616.81,-756.24 -697,-751.36 -940.12,-649.8 -845,-631.54 -732.94,-615 -695,-614.06 -647,-529.36 -609.06,-528.42 -561.94,-385.65 -526.81,-385.88 -491.67,-386.12
  other v5: -614,-164 -644,-134.36 -616,-133.36
pads on no net: IC1.26
copper on no net:
  other v1: -1290,-384.06

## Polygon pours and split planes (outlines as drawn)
VM on VM "VM_L03_P104" (solid, pour order 104): -1450,-1110.63 -1450,10.63 cw(c-1410.63,10.63) -1410.63,50 10.63,50 cw(c10.63,10.63) 50,10.63 50,-1110.63 cw(c10.63,-1110.63) 10.63,-1150 -1410.63,-1150 cw(c-1410.63,-1110.63)
GND on GND "GND_L02_P103" (solid, pour order 103): -1450,-1110.63 -1450,10.63 cw(c-1410.63,10.63) -1410.63,50 10.63,50 cw(c10.63,10.63) 50,10.63 50,-1110.63 cw(c10.63,-1110.63) 10.63,-1150 -1410.63,-1150 cw(c-1410.63,-1110.63)
SRB on Top "SRB_L01_P090" (solid, pour order 90): -577.02,-590.31 -609.22,-590.31 ccw(c-609.23,-626.38) -634.73,-600.88 -643.02,-609.17 ccw(c-625.87,-626.31) -650.12,-626.31 ccw(c-624.16,-626.31) -642.52,-644.66 -633.59,-653.59 ccw(c-591.81,-611.81) -591.81,-670.9 -541.47,-670.9 -526.81,-656.24 -526.81,-617.45 -537.63,-606.63 ccw(c-577.02,-646.03)
A2 on Top "A2_L01_P095" (solid, pour order 95): -350.47,29 -350.47,-231 -85.47,-231 -85.47,29
A1 on Top "A1_L01_P097" (solid, pour order 97): -350.47,-251 -350.47,-511 -85.47,-511 -85.47,-251
B1 on Top "B1_L01_P098" (solid, pour order 98): -350.47,-591 -350.47,-851 -85.47,-851 -85.47,-591
B2 on Top "B2_L01_P096" (solid, pour order 96): -350.47,-871 -350.47,-1131 -85.47,-1131 -85.47,-871
VM on Top "VM_L01_P091" (solid, pour order 91): -501.94,-1061.36 -572.34,-1061.36 cw(c-572.34,-1035.63) -590.54,-1053.82 -597.98,-1046.38 ccw(c-648.32,-1096.71) -648.32,-1025.53 -706.84,-1025.53 cw(c-706.84,-999.2) -733.17,-999.2 -733.17,-958.53 cw(c-713,-958.53) -713,-938.36 -635.04,-938.36 cw(c-635.04,-953.4) -620,-953.4 -620,-958.36 ccw(c-596.58,-958.36) -596.58,-981.78 -478.58,-981.78 -478.58,-1038.01
VM on Top "VM_L01_P093" (solid, pour order 93): -526.81,-118.29 -680.93,-118.29 -733,-170.36 -631.97,-271.4 -526.81,-166.24
SRA on Top "SRA_L01_P099" (solid, pour order 99): -535,5 -708.33,5 ccw(c-708.33,-119.75) -796.54,-31.54 -1051.72,-286.72 cw(c-1120,-218.44) -1120,-315 -1120,-340.37 -1100.37,-360 -942.17,-360 -658.84,-76.67 -586.47,-76.67 -535,-25.21
VM on Top "VM_L01_P092" (solid, pour order 92): -526.81,-425.88 -527.16,-426.24 -576.81,-426.24 -576.81,-341.24 -571.81,-336.24 -478.58,-336.24 -478.58,-418.01 -486.81,-426.24
SRA on Top "SRA_L01_P094" (solid, pour order 94): -526.81,-291.24 -526.81,-336.12 -576.81,-336.12 -576.81,-215.08 -562.97,-201.24 -483.58,-201.24 -478.58,-206.24 -478.58,-286.24
VM on Top "VM_L01_P100" (solid, pour order 100): -545.38,-462.8 -633.37,-462.8 -746.81,-576.24 -766.74,-596.17 -766.74,-628.61 -774.37,-636.24 -779.07,-631.54 -817.16,-631.54 -817.16,-613.21 -828.13,-602.23 -954.76,-602.23 -954.76,-664.84 -882.2,-737.4 -819.6,-737.4 -735.76,-821.24 -516.81,-821.24 -516.81,-721.24 -545.38,-692.67
SRB on Top "SRB_L01_P101" (solid, pour order 101): -493.58,-926.24 -478.58,-911.24 -478.58,-826.24 -523.58,-781.24 -820.76,-781.24 -856.88,-745.12 -1151.81,-745.12 -1151.81,-781.24 -1025.67,-907.37 ccw(c-934.01,-815.71) -934.01,-945.34 -755.6,-945.34 ccw(c-755.6,-907.61) -728.93,-934.29 cw(c-709.48,-953.75) -709.48,-926.23
GND on Top "GND_L01_P102" (solid, pour order 102): -1450,-1110.63 -1450,10.63 cw(c-1410.63,10.63) -1410.63,50 10.63,50 cw(c10.63,10.63) 50,10.63 50,-1110.63 cw(c10.63,-1110.63) 10.63,-1150 -1410.63,-1150 cw(c-1410.63,-1110.63)
B1 on Bottom "B1_L04_P105" (solid, pour order 105): -85.15,-418.7 cw(c-122.76,-418.71) -90.39,-437.86 cw(c-265.59,-334.19) -122.82,-479.3 -203.81,-559 cw(c-281.96,-479.57) -281.96,-591 -292,-591 -292,-810 -85,-810 -85,-767.76 cw(c308.62,-767.77) -74.38,-676.96 -28.46,-483.27 cw(c-1.36,-489.7) -2.5,-461.87 50,-459.72 50,-331.57 -17.47,-341.07 ccw(c-6.51,-418.94)
B1 on Bottom "B1_L04_P110" (solid, pour order 110): -350.47,-591 -350.47,-851 -85.47,-851 -85.47,-591
A1 on Bottom "A1_L04_P106" (solid, pour order 106): 50,-153 21.3,-153 ccw(c21.27,-303.69) 16.98,-153.06 ccw(c20.49,-277.07) -60.53,-183.13 -115.47,-230.51 cw(c-170.59,-166.61) -170.59,-251 -187,-251 -187,-391 -86.35,-391 cw(c303.9,-512.45) -50,-308 -34.15,-282.71 cw(c5.06,-307.28) 5.05,-261.01 50,-261
B2 on Bottom "B2_L04_P107" (solid, pour order 107): -350.47,-871 -350.47,-1131 -85.47,-1131 -85.47,-871
A1 on Bottom "A1_L04_P109" (solid, pour order 109): -350.47,-251 -350.47,-511 -85.47,-511 -85.47,-251
A2 on Bottom "A2_L04_P108" (solid, pour order 108): -350.47,29 -350.47,-231 -85.47,-231 -85.47,29
GND on Bottom "GND_L04_P111" (solid, pour order 111): -1450,-1110.63 -1450,10.63 cw(c-1410.63,10.63) -1410.63,50 10.63,50 cw(c10.63,10.63) 50,10.63 50,-1110.63 cw(c10.63,-1110.63) 10.63,-1150 -1410.63,-1150 cw(c-1410.63,-1110.63)

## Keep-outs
Keep-Out Layer:
  the board outline again, w4

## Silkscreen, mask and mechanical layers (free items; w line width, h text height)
Top Overlay:
  lines w4: -118,-536 -90,-536 ; -118,-443 -90,-443 ; -118,-350 -90,-350 ; -118,-257 -90,-257 ; -118,-164 -90,-164
  text "VS" at -130.01,-15 h37
  text "VCC_IO" at -1325,-20 h35
  text "'.BoardName'" at -1011,-24.36 h34
  text "V.BoardVersion" at -728,-76.36 h34
  text "GND" at -1325,-116 h37.4
  text "GND" at -69,-150 h40 r90
  text "DIR" at -1325,-222.99 h40
  text "STEP" at -1325,-320 h40
  text "SDO" at -1335,-419.99 h40
  text "SDI" at -1325,-519.99 h40
  text "A / 1 / A / 2 / B / 1 / B / 2" at -122,-531.67 h30
  text "SCK" at -1325,-619.99 h40
  text "GND" at -69,-700 h40 r90
  text "CSN" at -1325,-719.99 h40
  text "GND" at -1325,-820 h40
  text "GND" at -69,-900 h40 r90
  text "DRV_ENN" at -1316,-939 h33 r30
  text "CLK16" at -1311,-1019 h40 r30
  text "GND" at -69,-1100 h40 r90
  text "SG_TST" at -1336.81,-1121.24 h35
Bottom Overlay:
  lines w8: -50,-550 -50,-150
  text "VCC_IO" at -1105.07,-20 h40
  text "VS" at -73.37,-20 h40
  text "GND" at -73.37,-97 h40
  text "GND" at -1218.37,-120 h40
  text "DIR" at -1225.03,-219.99 h40
  text "A1" at -73.53,-220 h40
  text "STEP" at -1178.38,-320 h40
  text "A2" at -73.53,-320 h40
  text "SDO" at -1218.37,-419.99 h40
  text "B1" at -73.53,-420 h40
  text "'.BoardName'_V'.BoardVersion'" at -250.76,-499.3 h35
  text "SDI" at -1231.7,-519.99 h40
  text "B2" at -73.53,-520 h40
  text "IC name: '.Chip'" at -246,-568.36 h50
  text "Supply range: VS = '.VS'" at -245.9,-607.42 h50
  text "SCK" at -1218.37,-619.99 h40
  text "GND" at -73.53,-619.99 h40
  text "Max. current: IRMS = '.IRMS'" at -246,-650.36 h50
  text "CSN" at -1218.37,-719.99 h40
  text "GND" at -73.53,-719.99 h40
  text "GND" at -1218.37,-820 h40
  text "GND" at -73.53,-819.99 h40
  text "DRV_ENN" at -1105.07,-911 h33
  text "GND" at -73.53,-919.99 h40
  text "CLK16" at -1145.06,-1020 h40
  text "GND" at -73.53,-1019.99 h40
  text "SG_TST" at -1098.41,-1119.99 h40
  text "GND" at -73.53,-1119.99 h40
TopAsm:
  text ".BoardName" at -1298,-257.36 h50 r270
  text ".BoardVersion" at -1301,-947.36 h50 r270

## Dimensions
10.63,-1150 to 10.63,50 on Dimension
-1450,10.63 to 50,10.63 on Dimension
